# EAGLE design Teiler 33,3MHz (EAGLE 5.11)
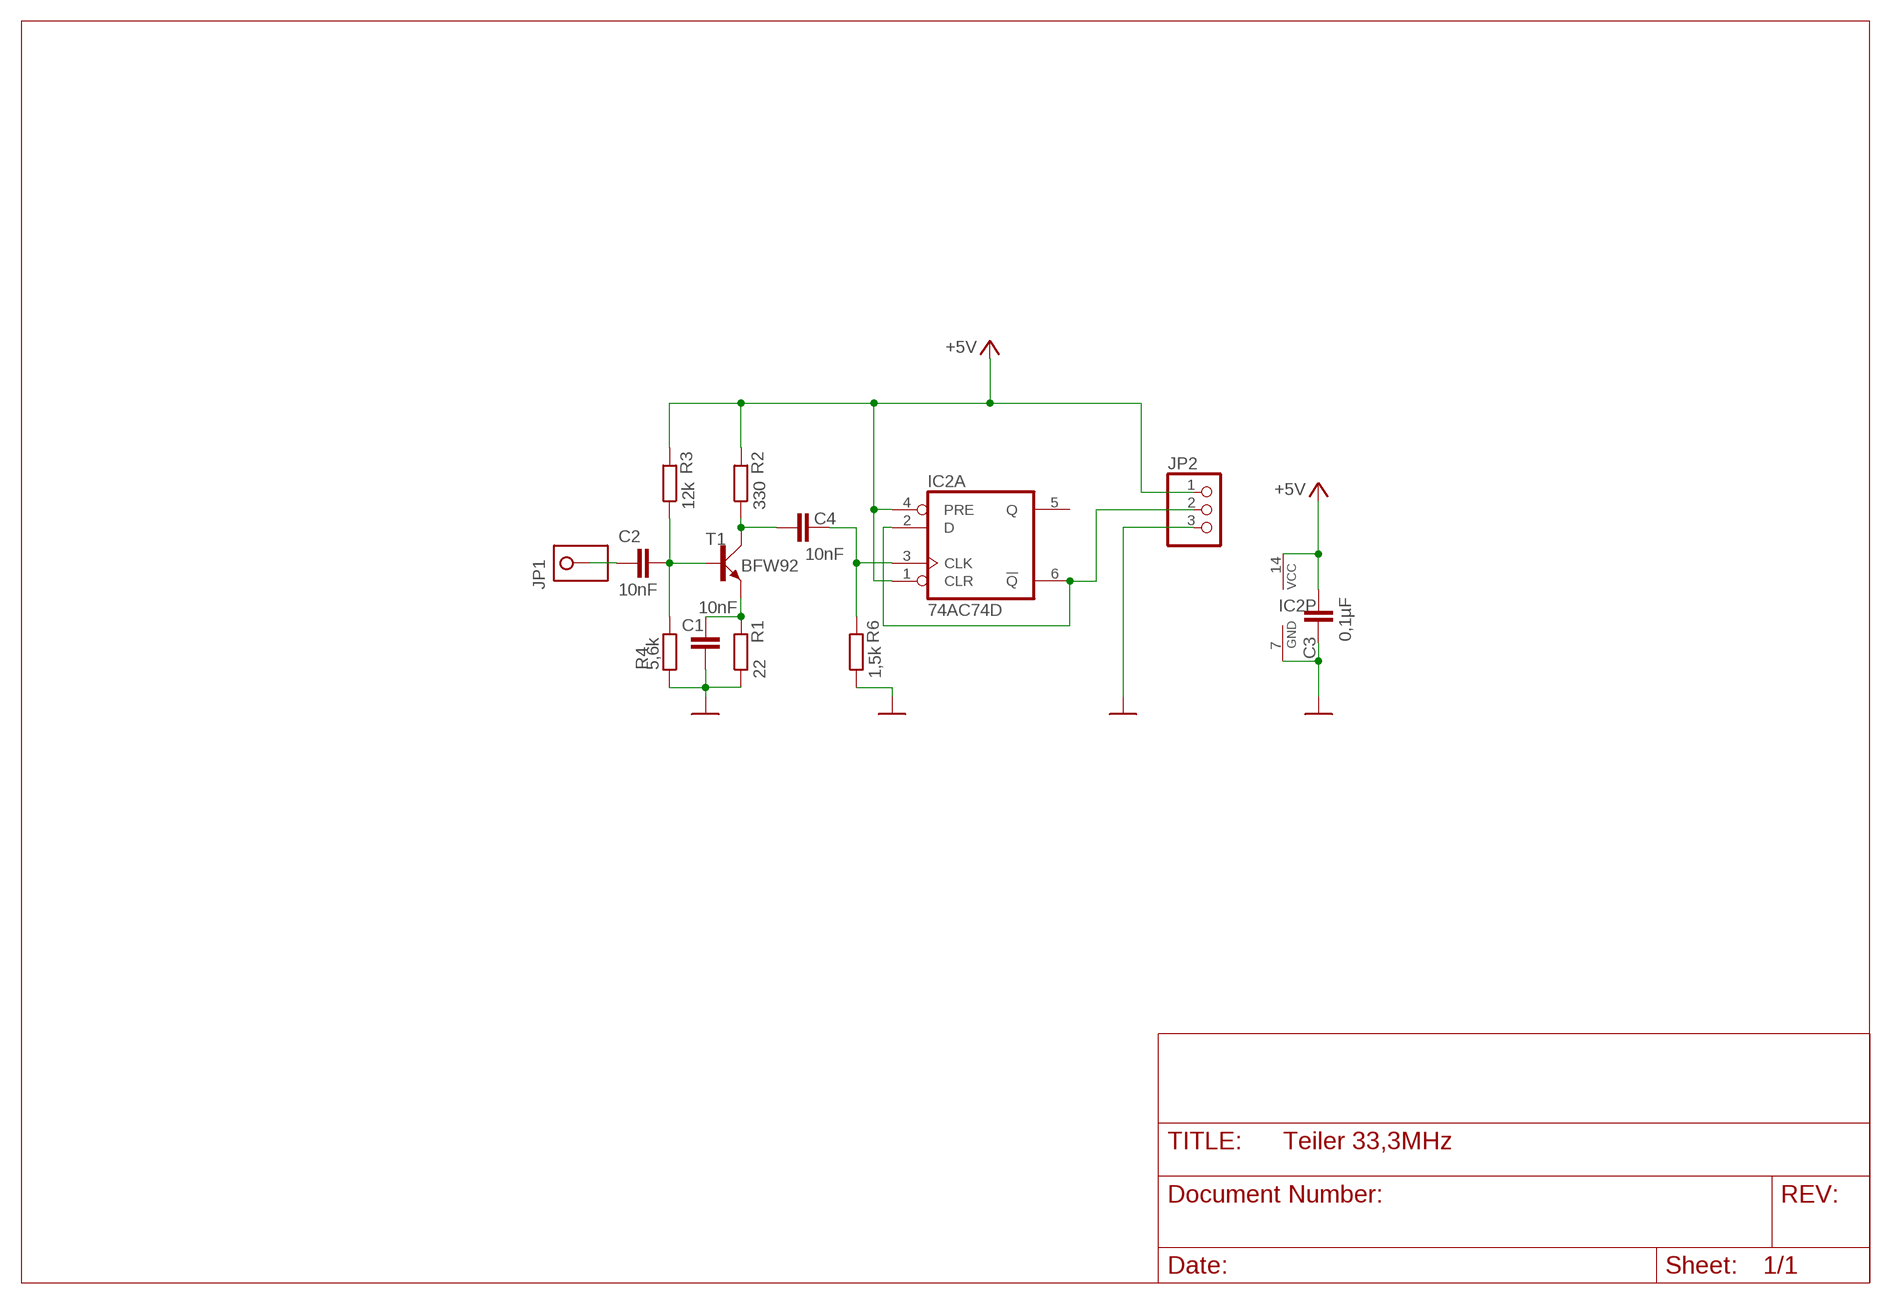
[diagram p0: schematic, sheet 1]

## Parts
C1  10nF  C-EUC0805  [C0805]
C2  10nF  C-EUC0805  [C0805]
C3  0,1µF  C-EUC0805  [C0805]
C4  10nF  C-EUC0805  [C0805]
IC2  74AC74D  [SO14]
JP1  LÖTPUNKT1  [PUNKT1]
JP2  PINHD-1X03_2.54-90°-S  [1X03/90-S]
R1  22  R-EU_R0805  [R0805]
R2  330  R-EU_R0805  [R0805]
R3  12k  R-EU_R0805  [R0805]
R4  5,6k  R-EU_R0805  [R0805]
R6  1,5k  R-EU_R0805  [R0805]
T1  BFW92  [TO-50]

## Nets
+5V: C3.1 IC2.1(A:CLR) IC2.4(A:PRE) IC2.14(P:VCC) JP2.1 R2.2 R3.2
GND: C1.1 C3.2 IC2.7(P:GND) JP2.3 R1.1 R4.1 R6.1
N$2: IC2.2(A:D) IC2.6(A:!Q) JP2.2
N$3: C1.2 R1.2 T1.2-E(E)
N$4: C4.1 IC2.3(A:CLK) R6.2
N$5: C2.1 R3.1 R4.2 T1.3-B(B)
N$6: C2.2 JP1.P$1
N$8: C4.2 R2.1 T1.1-C(C)
Unconnected: IC2.5(A:Q) IC2.8(B:!Q) IC2.9(B:Q) IC2.10(B:PRE) IC2.11(B:CLK) IC2.12(B:D) IC2.13(B:CLR)

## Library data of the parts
C1-C4 = rcl:C-EU: CAPACITOR, European symbol
IC2 = 74xx-eu:74*74: Dual D type positive edge triggered FLIP FLOP, preset and clear
JP1 = 1Eigene:LÖTPUNKT1
JP2 = pinhead-2:PINHD-1X03: PIN HEADER
R1-R4 R6 = rcl:R-EU_: RESISTOR, European symbol
T1 = 1Eigene:BFW92

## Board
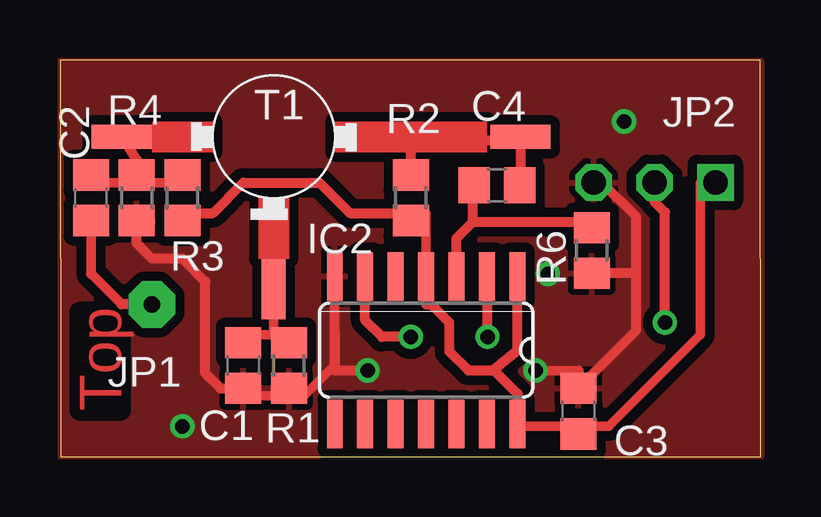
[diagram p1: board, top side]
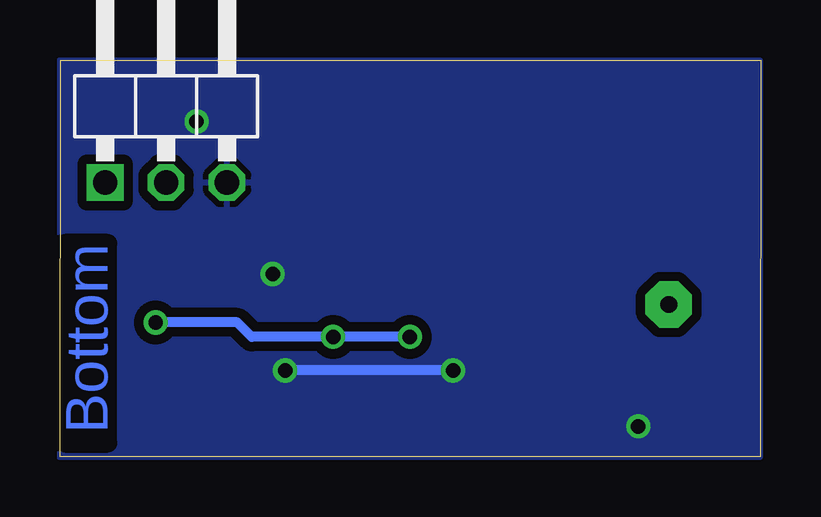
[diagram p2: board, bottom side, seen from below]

Size 29.22 x 16.54 mm. Coordinates in mm from the lower left corner, seen from the top.
Outline: 0.03,0 29.22,0 29.19,16.54 0,16.54 0.03,0
Copper layers (1*16): Top 0.035mm / dielectric 1.5mm / Bottom 0.035mm
Design rules "default *": minimum track width 0.4mm, minimum drill 0.7mm, track to track 0.4mm, track to pad 0.4mm, pad to pad 0.4mm, via to via 0.4mm, smd to smd 0.4mm, copper to edge 0mil, drill to drill 8mil, minimum pad ring 10mil, minimum via ring 8mil, stop-mask expansion 4mil, vias tented up to drill 0mil, thermal gap 10mil

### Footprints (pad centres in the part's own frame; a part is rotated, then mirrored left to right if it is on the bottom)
C0805 = smd 1.3 x 1.5: 1 -0.95,0; 2 0.95,0
SO14 = smd 0.66 x 2.032: 1 -3.81,-3.073; 2 -2.54,-3.073; 3 -1.27,-3.073; 4 0,-3.073; 5 1.27,-3.073; 6 2.54,-3.073; 7 3.81,-3.073; 8 3.81,3.073; 9 2.54,3.073; 10 1.27,3.073; 11 0,3.073; 12 -1.27,3.073; 13 -2.54,3.073; 14 -3.81,3.073
PUNKT1 = drill 0.7 pad 1.93 octagon: P$1 0,0
1X03/90-S = drill 1.016 square: 1 -2.54,-3.81 | drill 1.016 octagon: 2 0,-3.81; 3 2.54,-3.81
R0805 = smd 1.3 x 1.5: 1 -0.95,0; 2 0.95,0
TO-50 = smd 1 x 2.5: 1-C 0,-10.285; 3-B 0,6.35 | smd 2.5 x 1: 2-E -6.35,0

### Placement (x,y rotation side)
C1  7.65,3.81 90 top
C2  1.3,10.79 270 top
C3  21.62,1.91 90 top
C4  18.22,11.31 0 top
IC2  15.27,4.45 180 top
JP1  3.84,6.35 0 top
JP2  24.79,15.24 0 bottom
R1  9.55,3.81 90 top
R2  14.63,10.79 270 top
R3  5.11,10.79 270 top
R4  3.2,10.79 90 top
R6  22.17,8.6 90 top
T1  8.92,13.34 90 top

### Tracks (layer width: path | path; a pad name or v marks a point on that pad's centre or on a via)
+5V
  Top 0.4: 21.62,1.27 19.08,1.27 IC2.14 19.08,2.54 | R3.2 5.11,10.16 | 14,10.16 R2.2 15.27,10.16 IC2.4 15.27,6.35 | 21.62,1.27 22.89,1.27 26.7,5.08 26.7,11.43 JP2.1 | 21.62,1.27 C3.1
  Top 0.406: IC2.1 19.08,4.45 18.07,3.64 | 18.07,3.64 18.02,3.6 17.03,3.6 16.23,4.4 16.23,5.6 15.48,6.35 15.27,6.35 | 19.08,2.54 19.08,2.63 18.07,3.64 | 5.11,10.16 6.38,10.16 7.65,11.43 10.82,11.43 12.09,10.16 14,10.16
GND  (via drill 0.6)
  Top 0.4: C1.1 7.65,2.54 8.92,2.54 R1.1 10.19,2.54 11.46,3.81 11.46,5.2 IC2.7 11.46,7.62 | C3.2 21.62,2.54
  Top 0.406: R4.1 3.2,8.89 3.84,8.26 5.11,8.26 6.06,7.3 6.06,3.49 6.69,2.86 C1.1 | JP2.3 22.6,11.43 24.03,10 24.03,7.6 | 24.03,7.6 24.03,5.26 C3.2 21.62,3.59 v19.83,3.6 | R6.1 23.98,7.64 24.03,7.6 | v12.83,3.6 11.46,3.6 11.46,5.2
  Bottom 0.406: v12.83,3.6 v19.83,3.6
  other vias: 20.35,7.62 23.52,13.97 5.11,1.27
  pour Bottom: 0.03,16.51 29.24,16.51 29.24,0 0.03,0
  pour Top: 0.03,16.51 29.24,16.51 29.24,0 0.03,0
N$2  (via drill 0.6)
  Top 0.406: IC2.6 12.73,5.7 13.43,5 v14.63,5 | v17.83,5 17.83,7.5 IC2.2 | JP2.2 24.79,10.63 25.23,10.2 v25.23,5.6
  Bottom 0.406: v14.63,5 v17.83,5 21.23,5 21.83,5.6 v25.23,5.6
N$3
  Top 0.4: 8.92,5.08 7.65,5.08 C1.2 | R1.2 8.92,5.08 | 8.92,5.08 T1.2-E
N$4
  Top 0.4: IC2.3 16.54,7.62
  Top 0.406: 16.54,7.62 16.54,9.11 17.23,9.8 | 21.87,9.85 R6.2 21.92,9.8 17.23,9.8 | 17.23,9.8 17.23,11.27 C4.1
N$5
  Top 0.4: C2.1 1.3,11.43 2.57,11.43 R4.2 3.84,11.43 5.11,11.43 R3.1
  Top 0.406: T1.3-B 3.2,12.38 R4.2
N$6
  Top 0.4: 1.3,7.62 C2.2 1.3,10.16
  Top 0.406: JP1.P$1 2.57,6.35 1.3,7.62
N$8
  Top 0.406: C4.2 19.2,12.26 T1.1-C 19.07,13.2 15.03,13.2 14.63,12.8 R2.1
(copper drawn outside any net)
  shapes: Top area x3

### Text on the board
Top: Top
Bottom: Bottom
